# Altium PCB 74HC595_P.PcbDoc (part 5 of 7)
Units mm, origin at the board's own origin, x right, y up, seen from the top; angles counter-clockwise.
Board outline 89.11 x 89.03 mm, 2 copper layers (Top Layer, Bottom Layer); 552 components, 23 nets, 1488 pads, 408 vias.
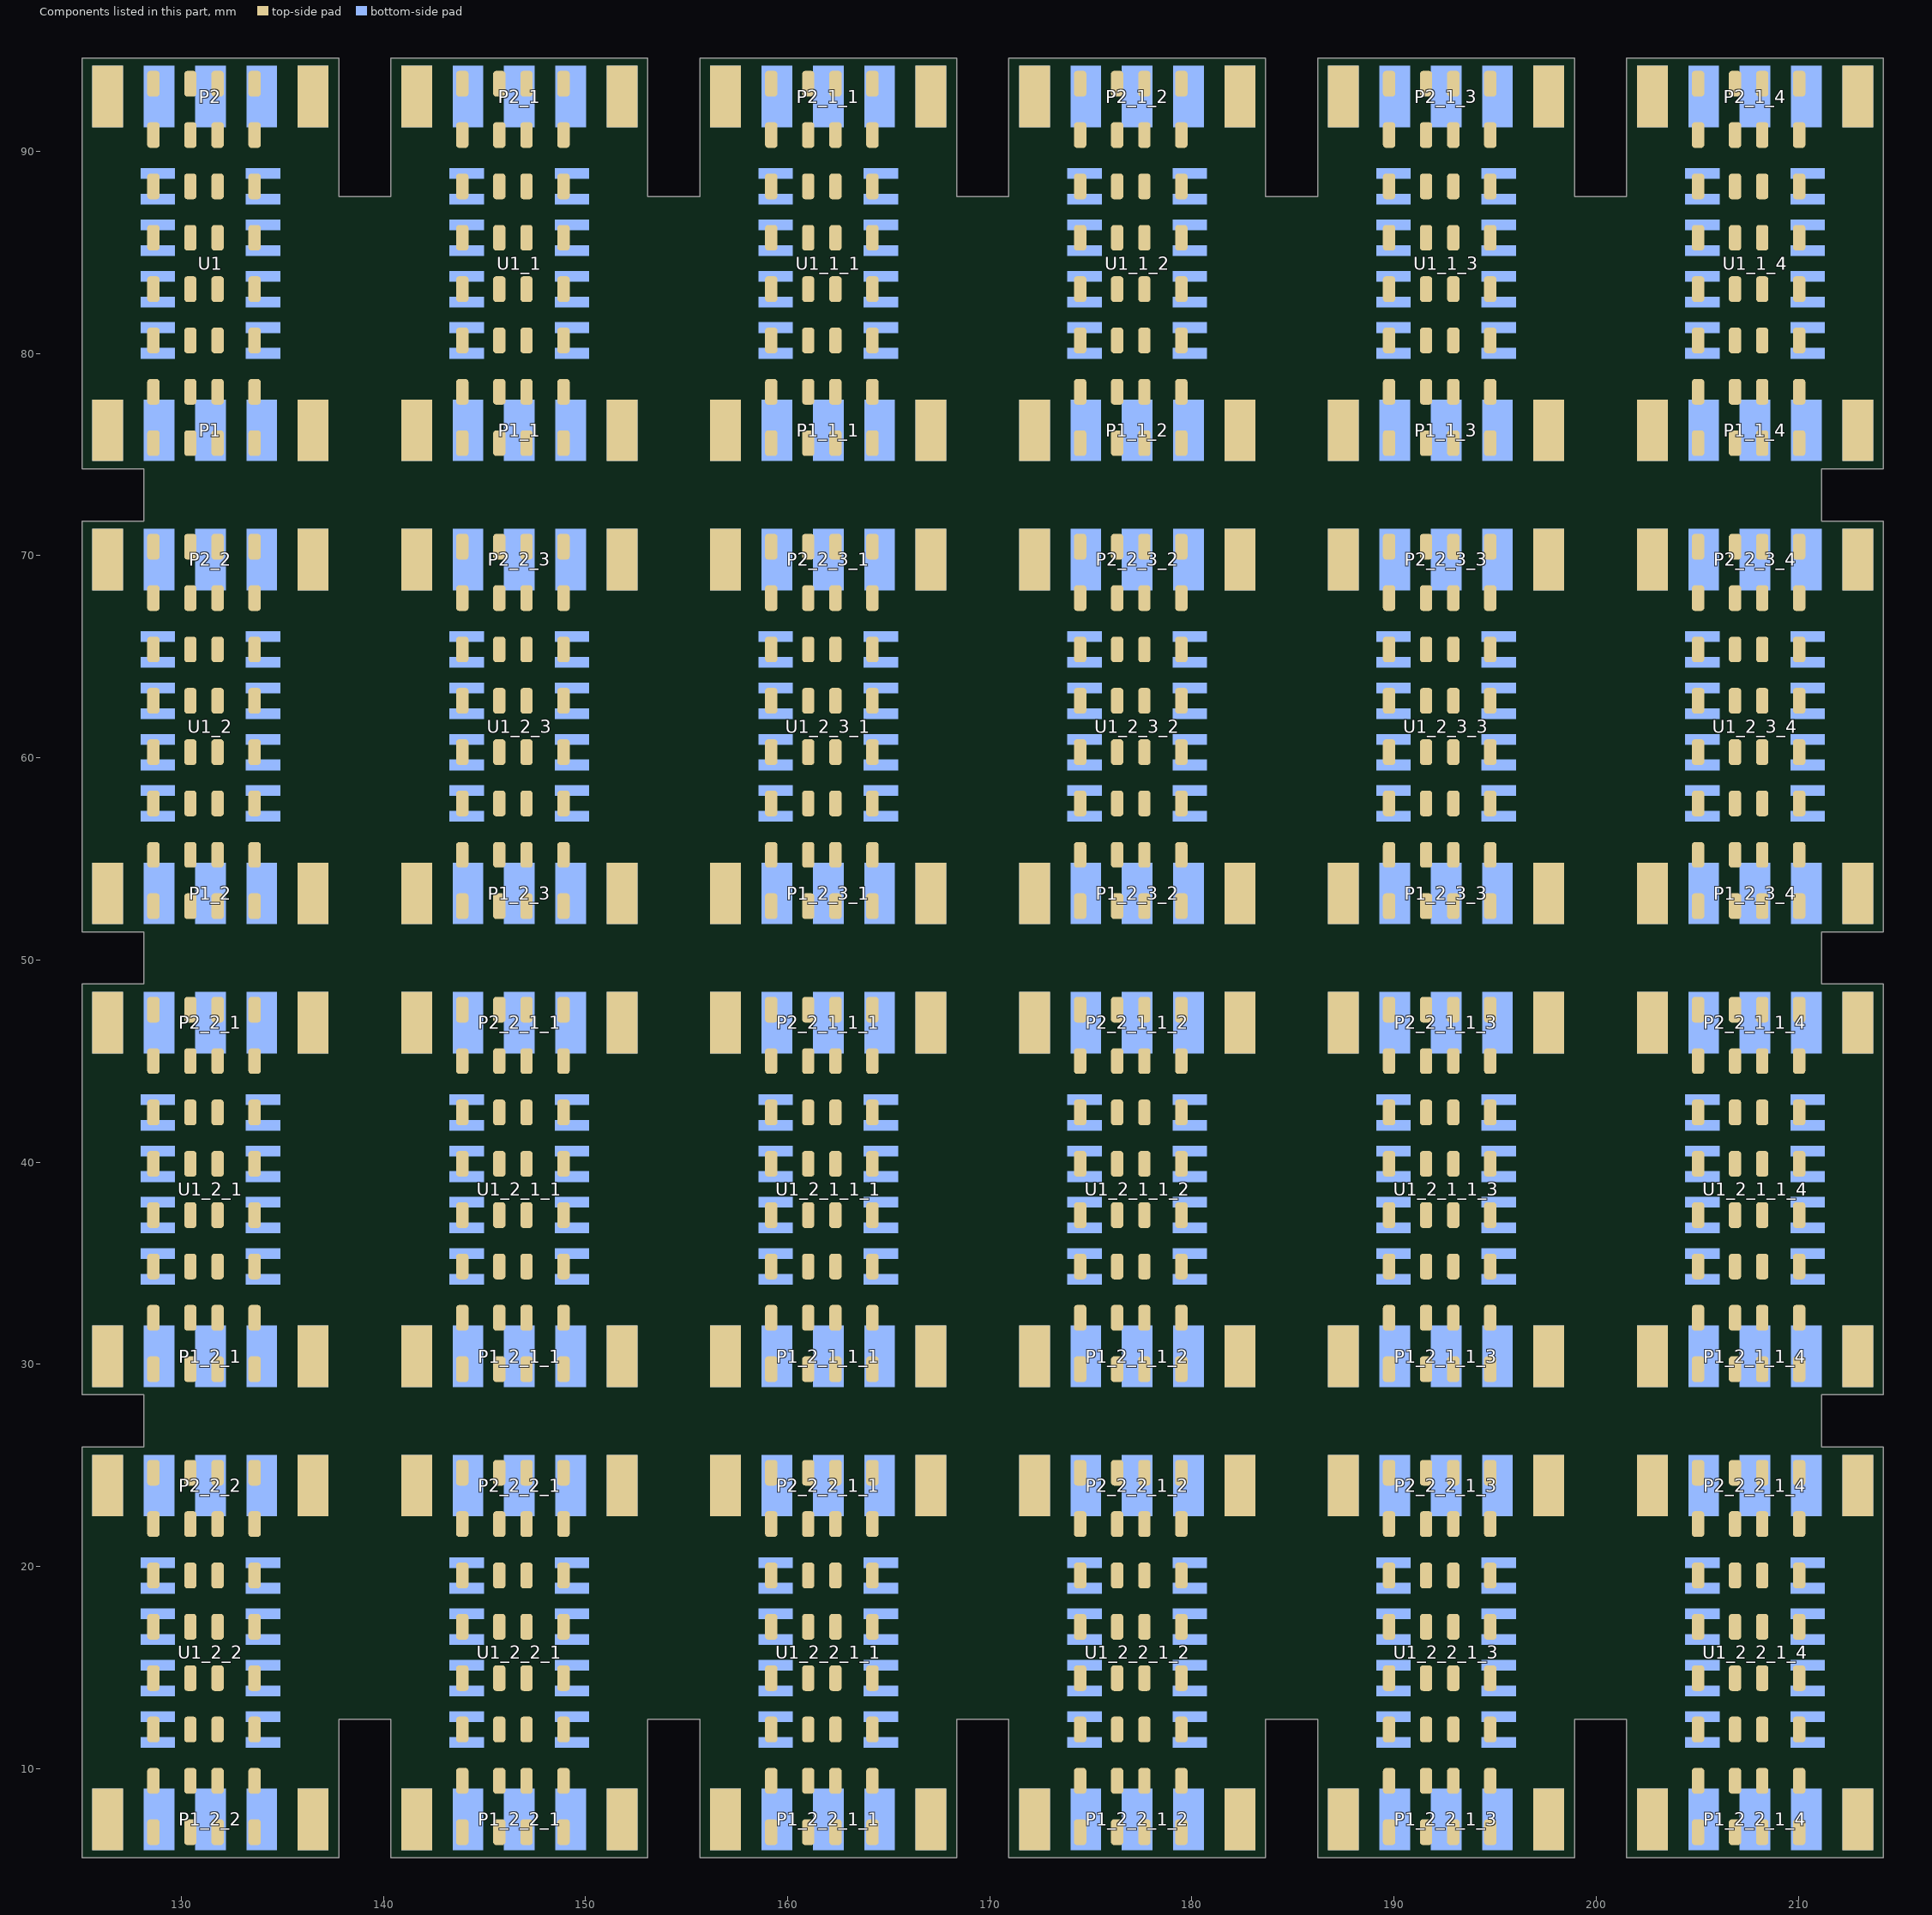
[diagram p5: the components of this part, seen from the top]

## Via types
v1: diameter 0.635, hole 0.381, Top Layer to Bottom Layer, 408 vias

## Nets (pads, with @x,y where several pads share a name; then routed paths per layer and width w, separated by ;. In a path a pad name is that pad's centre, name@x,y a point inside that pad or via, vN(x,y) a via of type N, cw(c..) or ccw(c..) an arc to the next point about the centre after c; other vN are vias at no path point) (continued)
copper on no net: | length 5395.2
  Top Layer w0.381: v1(126.746,16.765) v1(126.746,18.67) ; v1(126.746,39.667) v1(126.746,41.572) ; v1(126.746,62.569) v1(126.746,64.474) ; v1(127.508,15.749) v1(127.508,19.559) ; v1(127.508,38.651) v1(127.508,42.461) ; v1(127.508,61.553) v1(127.508,65.363) ; 130.454,6.859 131.801,6.859 ; 130.454,9.399 131.801,9.399 ; 130.454,11.939 131.801,11.939 ; 130.454,14.479 131.801,14.479 ; 130.454,17.019 131.801,17.019 ; 130.454,19.559 131.801,19.559 ; 130.454,22.099 131.801,22.099 ; 130.454,24.639 131.801,24.639 ; 130.454,29.761 131.801,29.761 ; 130.454,32.301 131.801,32.301 ; 130.454,34.841 131.801,34.841 ; 130.454,37.381 131.801,37.381 ; 130.454,39.921 131.801,39.921 ; 130.454,42.461 131.801,42.461 ; 130.454,45.001 131.801,45.001 ; 130.454,47.541 131.801,47.541 ; 130.454,52.663 131.801,52.663 ; 130.454,55.203 131.801,55.203 ; 130.454,57.743 131.801,57.743 ; 130.454,60.283 131.801,60.283 ; 130.454,62.823 131.801,62.823 ; 130.454,65.363 131.801,65.363 ; 130.454,67.903 131.801,67.903 ; 130.454,70.443 131.801,70.443 ; v1(131.191,15.749) 132.334,15.749 132.715,16.13 132.715,20.321 132.207,20.829 v1(131.191,20.829) ; v1(131.191,38.651) 132.334,38.651 132.715,39.032 132.715,43.223 132.207,43.731 v1(131.191,43.731) ; v1(131.191,61.553) 132.334,61.553 132.715,61.934 132.715,66.125 132.207,66.633 v1(131.191,66.633) ; 133.629,6.859 133.629,7.773 134.493,8.637 134.493,10.406 135.128,11.041 135.128,11.812 v1(135.89,12.574) ; 133.629,9.399 133.629,10.44 134.379,11.19 134.379,12.206 v1(136.017,13.844) ; 133.629,11.939 133.629,12.853 v1(135.89,15.114) ; 133.629,14.758 133.629,14.479 133.985,14.479 v1(135.89,16.384) ; 133.629,17.019 135.255,17.019 v1(135.89,17.654) ; 133.629,19.559 135.255,19.559 v1(135.89,18.924) ; 133.629,21.885 133.629,22.099 133.629,21.312 134.747,20.194 v1(135.89,20.194) ; 133.629,24.639 133.629,23.725 134.62,22.734 134.62,21.972 135.128,21.464 v1(135.89,21.464) ; 133.629,29.761 133.629,30.675 134.493,31.539 134.493,33.308 135.128,33.943 135.128,34.714 v1(135.89,35.476) ; 133.629,32.301 133.629,33.342 134.379,34.092 134.379,35.108 v1(136.017,36.746) ; 133.629,34.841 133.629,35.755 v1(135.89,38.016) ; 133.629,37.66 133.629,37.381 133.985,37.381 v1(135.89,39.286) ; 133.629,39.921 135.255,39.921 v1(135.89,40.556) ; 133.629,42.461 135.255,42.461 v1(135.89,41.826) ; 133.629,44.787 133.629,45.001 133.629,44.214 134.747,43.096 v1(135.89,43.096) ; 133.629,47.541 133.629,46.627 134.62,45.636 134.62,44.874 135.128,44.366 v1(135.89,44.366) ; 133.629,52.663 133.629,53.577 134.493,54.441 134.493,56.21 135.128,56.845 135.128,57.616 v1(135.89,58.378) ; 133.629,55.203 133.629,56.244 134.379,56.994 134.379,58.01 v1(136.017,59.648) ; 133.629,57.743 133.629,58.657 v1(135.89,60.918) ; 133.629,60.562 133.629,60.283 133.985,60.283 v1(135.89,62.188) ; 133.629,62.823 135.255,62.823 v1(135.89,63.458) ; 133.629,65.363 135.255,65.363 v1(135.89,64.728) ; 133.629,67.689 133.629,67.903 133.629,67.116 134.747,65.998 v1(135.89,65.998) ; 133.629,70.443 133.629,69.529 134.62,68.538 134.62,67.776 135.128,67.268 v1(135.89,67.268) ; v1(135.89,11.304) 137.033,11.304 ; v1(135.89,34.206) 137.033,34.206 ; v1(135.89,57.108) 137.033,57.108 ; v1(142.028,16.765) v1(142.028,18.67) ; v1(142.028,39.667) v1(142.028,41.572) ; v1(142.028,62.569) v1(142.028,64.474) ; v1(142.028,85.471) v1(142.028,87.376) ; v1(142.79,15.749) v1(142.79,19.559) ; v1(142.79,38.651) v1(142.79,42.461) ; v1(142.79,61.553) v1(142.79,65.363) ; v1(142.79,84.455) v1(142.79,88.265) ; 145.736,6.859 147.083,6.859 ; 145.736,9.399 147.083,9.399 ; 145.736,11.939 147.083,11.939 ; 145.736,14.479 147.083,14.479 ; 145.736,17.019 147.083,17.019 ; 145.736,19.559 147.083,19.559 ; 145.736,22.099 147.083,22.099 ; 145.736,24.639 147.083,24.639 ; 145.736,29.761 147.083,29.761 ; 145.736,32.301 147.083,32.301 ; 145.736,34.841 147.083,34.841 ; 145.736,37.381 147.083,37.381 ; 145.736,39.921 147.083,39.921 ; 145.736,42.461 147.083,42.461 ; 145.736,45.001 147.083,45.001 ; 145.736,47.541 147.083,47.541 ; 145.736,52.663 147.083,52.663 ; 145.736,55.203 147.083,55.203 ; 145.736,57.743 147.083,57.743 ; 145.736,60.283 147.083,60.283 ; 145.736,62.823 147.083,62.823 ; 145.736,65.363 147.083,65.363 ; 145.736,67.903 147.083,67.903 ; 145.736,70.443 147.083,70.443 ; 145.736,75.565 147.083,75.565 ; 145.736,78.105 147.083,78.105 ; 145.736,80.645 147.083,80.645 ; 145.736,83.185 147.083,83.185 ; 145.736,85.725 147.083,85.725 ; 145.736,88.265 147.083,88.265 ; 145.736,90.805 147.083,90.805 ; 145.736,93.345 147.083,93.345 ; v1(146.473,15.749) 147.616,15.749 147.997,16.13 147.997,20.321 147.489,20.829 v1(146.473,20.829) ; v1(146.473,38.651) 147.616,38.651 147.997,39.032 147.997,43.223 147.489,43.731 v1(146.473,43.731) ; v1(146.473,61.553) 147.616,61.553 147.997,61.934 147.997,66.125 147.489,66.633 v1(146.473,66.633) ; v1(146.473,84.455) 147.616,84.455 147.997,84.836 147.997,89.027 147.489,89.535 v1(146.473,89.535) ; 148.911,6.859 148.911,7.773 149.775,8.637 149.775,10.406 150.41,11.041 150.41,11.812 v1(151.172,12.574) ; 148.911,9.399 148.911,10.44 149.661,11.19 149.661,12.206 v1(151.299,13.844) ; 148.911,11.939 148.911,12.853 v1(151.172,15.114) ; 148.911,14.758 148.911,14.479 149.267,14.479 v1(151.172,16.384) ; 148.911,17.019 150.537,17.019 v1(151.172,17.654) ; 148.911,19.559 150.537,19.559 v1(151.172,18.924) ; 148.911,21.885 148.911,22.099 148.911,21.312 150.029,20.194 v1(151.172,20.194) ; 148.911,24.639 148.911,23.725 149.902,22.734 149.902,21.972 150.41,21.464 v1(151.172,21.464) ; 148.911,29.761 148.911,30.675 149.775,31.539 149.775,33.308 150.41,33.943 150.41,34.714 v1(151.172,35.476) ; 148.911,32.301 148.911,33.342 149.661,34.092 149.661,35.108 v1(151.299,36.746) ; 148.911,34.841 148.911,35.755 v1(151.172,38.016) ; 148.911,37.66 148.911,37.381 149.267,37.381 v1(151.172,39.286) ; 148.911,39.921 150.537,39.921 v1(151.172,40.556) ; 148.911,42.461 150.537,42.461 v1(151.172,41.826) ; 148.911,44.787 148.911,45.001 148.911,44.214 150.029,43.096 v1(151.172,43.096) ; 148.911,47.541 148.911,46.627 149.902,45.636 149.902,44.874 150.41,44.366 v1(151.172,44.366) ; 148.911,52.663 148.911,53.577 149.775,54.441 149.775,56.21 150.41,56.845 150.41,57.616 v1(151.172,58.378) ; 148.911,55.203 148.911,56.244 149.661,56.994 149.661,58.01 v1(151.299,59.648) ; 148.911,57.743 148.911,58.657 v1(151.172,60.918) ; 148.911,60.562 148.911,60.283 149.267,60.283 v1(151.172,62.188) ; 148.911,62.823 150.537,62.823 v1(151.172,63.458) ; 148.911,65.363 150.537,65.363 v1(151.172,64.728) ; 148.911,67.689 148.911,67.903 148.911,67.116 150.029,65.998 v1(151.172,65.998) ; 148.911,70.443 148.911,69.529 149.902,68.538 149.902,67.776 150.41,67.268 v1(151.172,67.268) ; 148.911,75.565 148.911,76.479 149.775,77.343 149.775,79.112 150.41,79.747 150.41,80.518 v1(151.172,81.28) ; 148.911,78.105 148.911,79.146 149.661,79.896 149.661,80.912 v1(151.299,82.55) ; 148.911,80.645 148.911,81.559 v1(151.172,83.82) ; 148.911,83.464 148.911,83.185 149.267,83.185 v1(151.172,85.09) ; 148.911,85.725 150.537,85.725 v1(151.172,86.36) ; 148.911,88.265 150.537,88.265 v1(151.172,87.63) ; 148.911,90.591 148.911,90.805 148.911,90.018 150.029,88.9 v1(151.172,88.9) ; 148.911,93.345 148.911,92.431 149.902,91.44 149.902,90.678 150.41,90.17 v1(151.172,90.17) ; v1(151.172,11.304) 152.315,11.304 ; v1(151.172,34.206) 152.315,34.206 ; v1(151.172,57.108) 152.315,57.108 ; v1(151.172,80.01) 152.315,80.01 ; v1(157.31,16.765) v1(157.31,18.67) ; v1(157.31,39.667) v1(157.31,41.572) ; v1(157.31,62.569) v1(157.31,64.474) ; v1(157.31,85.471) v1(157.31,87.376) ; v1(158.072,15.749) v1(158.072,19.559) ; v1(158.072,38.651) v1(158.072,42.461) ; v1(158.072,61.553) v1(158.072,65.363) ; v1(158.072,84.455) v1(158.072,88.265) ; 161.018,6.859 162.365,6.859 ; 161.018,9.399 162.365,9.399 ; 161.018,11.939 162.365,11.939 ; 161.018,14.479 162.365,14.479 ; 161.018,17.019 162.365,17.019 ; 161.018,19.559 162.365,19.559 ; 161.018,22.099 162.365,22.099 ; 161.018,24.639 162.365,24.639 ; 161.018,29.761 162.365,29.761 ; 161.018,32.301 162.365,32.301 ; 161.018,34.841 162.365,34.841 ; 161.018,37.381 162.365,37.381 ; 161.018,39.921 162.365,39.921 ; 161.018,42.461 162.365,42.461 ; 161.018,45.001 162.365,45.001 ; 161.018,47.541 162.365,47.541 ; 161.018,52.663 162.365,52.663 ; 161.018,55.203 162.365,55.203 ; 161.018,57.743 162.365,57.743 ; 161.018,60.283 162.365,60.283 ; 161.018,62.823 162.365,62.823 ; 161.018,65.363 162.365,65.363 ; 161.018,67.903 162.365,67.903 ; 161.018,70.443 162.365,70.443 ; 161.018,75.565 162.365,75.565 ; 161.018,78.105 162.365,78.105 ; 161.018,80.645 162.365,80.645 ; 161.018,83.185 162.365,83.185 ; 161.018,85.725 162.365,85.725 ; 161.018,88.265 162.365,88.265 ; 161.018,90.805 162.365,90.805 ; 161.018,93.345 162.365,93.345 ; v1(161.755,15.749) 162.898,15.749 163.279,16.13 163.279,20.321 162.771,20.829 v1(161.755,20.829) ; v1(161.755,38.651) 162.898,38.651 163.279,39.032 163.279,43.223 162.771,43.731 v1(161.755,43.731) ; v1(161.755,61.553) 162.898,61.553 163.279,61.934 163.279,66.125 162.771,66.633 v1(161.755,66.633) ; v1(161.755,84.455) 162.898,84.455 163.279,84.836 163.279,89.027 162.771,89.535 v1(161.755,89.535) ; 164.193,6.859 164.193,7.773 165.057,8.637 165.057,10.406 165.692,11.041 165.692,11.812 v1(166.454,12.574) ; 164.193,9.399 164.193,10.44 164.943,11.19 164.943,12.206 v1(166.581,13.844) ; 164.193,11.939 164.193,12.853 v1(166.454,15.114) ; 164.193,14.758 164.193,14.479 164.549,14.479 v1(166.454,16.384) ; 164.193,17.019 165.819,17.019 v1(166.454,17.654) ; 164.193,19.559 165.819,19.559 v1(166.454,18.924) ; 164.193,21.885 164.193,22.099 164.193,21.312 165.311,20.194 v1(166.454,20.194) ; 164.193,24.639 164.193,23.725 165.184,22.734 165.184,21.972 165.692,21.464 v1(166.454,21.464) ; 164.193,29.761 164.193,30.675 165.057,31.539 165.057,33.308 165.692,33.943 165.692,34.714 v1(166.454,35.476) ; 164.193,32.301 164.193,33.342 164.943,34.092 164.943,35.108 v1(166.581,36.746) ; 164.193,34.841 164.193,35.755 v1(166.454,38.016) ; 164.193,37.66 164.193,37.381 164.549,37.381 v1(166.454,39.286) ; 164.193,39.921 165.819,39.921 v1(166.454,40.556) ; 164.193,42.461 165.819,42.461 v1(166.454,41.826) ; 164.193,44.787 164.193,45.001 164.193,44.214 165.311,43.096 v1(166.454,43.096) ; 164.193,47.541 164.193,46.627 165.184,45.636 165.184,44.874 165.692,44.366 v1(166.454,44.366) ; 164.193,52.663 164.193,53.577 165.057,54.441 165.057,56.21 165.692,56.845 165.692,57.616 v1(166.454,58.378) ; 164.193,55.203 164.193,56.244 164.943,56.994 164.943,58.01 v1(166.581,59.648) ; 164.193,57.743 164.193,58.657 v1(166.454,60.918) ; 164.193,60.562 164.193,60.283 164.549,60.283 v1(166.454,62.188) ; 164.193,62.823 165.819,62.823 v1(166.454,63.458) ; 164.193,65.363 165.819,65.363 v1(166.454,64.728) ; 164.193,67.689 164.193,67.903 164.193,67.116 165.311,65.998 v1(166.454,65.998) ; 164.193,70.443 164.193,69.529 165.184,68.538 165.184,67.776 165.692,67.268 v1(166.454,67.268) ; 164.193,75.565 164.193,76.479 165.057,77.343 165.057,79.112 165.692,79.747 165.692,80.518 v1(166.454,81.28) ; 164.193,78.105 164.193,79.146 164.943,79.896 164.943,80.912 v1(166.581,82.55) ; 164.193,80.645 164.193,81.559 v1(166.454,83.82) ; 164.193,83.464 164.193,83.185 164.549,83.185 v1(166.454,85.09) ; 164.193,85.725 165.819,85.725 v1(166.454,86.36) ; 164.193,88.265 165.819,88.265 v1(166.454,87.63) ; 164.193,90.591 164.193,90.805 164.193,90.018 165.311,88.9 v1(166.454,88.9) ; 164.193,93.345 164.193,92.431 165.184,91.44 165.184,90.678 165.692,90.17 v1(166.454,90.17) ; v1(166.454,11.304) 167.597,11.304 ; v1(166.454,34.206) 167.597,34.206 ; v1(166.454,57.108) 167.597,57.108 ; v1(166.454,80.01) 167.597,80.01 ; v1(172.592,16.765) v1(172.592,18.67) ; v1(172.592,39.667) v1(172.592,41.572) ; v1(172.592,62.569) v1(172.592,64.474) ; v1(172.592,85.471) v1(172.592,87.376) ; v1(173.354,15.749) v1(173.354,19.559) ; v1(173.354,38.651) v1(173.354,42.461) ; v1(173.354,61.553) v1(173.354,65.363) ; v1(173.354,84.455) v1(173.354,88.265) ; 176.3,6.859 177.647,6.859 ; 176.3,9.399 177.647,9.399 ; 176.3,11.939 177.647,11.939 ; 176.3,14.479 177.647,14.479 ; 176.3,17.019 177.647,17.019 ; 176.3,19.559 177.647,19.559 ; 176.3,22.099 177.647,22.099 ; 176.3,24.639 177.647,24.639 ; 176.3,29.761 177.647,29.761 ; 176.3,32.301 177.647,32.301 ; 176.3,34.841 177.647,34.841 ; 176.3,37.381 177.647,37.381 ; 176.3,39.921 177.647,39.921 ; 176.3,42.461 177.647,42.461 ; 176.3,45.001 177.647,45.001 ; 176.3,47.541 177.647,47.541 ; 176.3,52.663 177.647,52.663 ; 176.3,55.203 177.647,55.203 ; 176.3,57.743 177.647,57.743 ; 176.3,60.283 177.647,60.283 ; 176.3,62.823 177.647,62.823 ; 176.3,65.363 177.647,65.363 ; 176.3,67.903 177.647,67.903 ; 176.3,70.443 177.647,70.443 ; 176.3,75.565 177.647,75.565 ; 176.3,78.105 177.647,78.105 ; 176.3,80.645 177.647,80.645 ; 176.3,83.185 177.647,83.185 ; 176.3,85.725 177.647,85.725 ; 176.3,88.265 177.647,88.265 ; 176.3,90.805 177.647,90.805 ; 176.3,93.345 177.647,93.345 ; v1(177.037,15.749) 178.18,15.749 178.561,16.13 178.561,20.321 178.053,20.829 v1(177.037,20.829) ; v1(177.037,38.651) 178.18,38.651 178.561,39.032 178.561,43.223 178.053,43.731 v1(177.037,43.731) ; v1(177.037,61.553) 178.18,61.553 178.561,61.934 178.561,66.125 178.053,66.633 v1(177.037,66.633) ; v1(177.037,84.455) 178.18,84.455 178.561,84.836 178.561,89.027 178.053,89.535 v1(177.037,89.535) ; 179.475,6.859 179.475,7.773 180.339,8.637 180.339,10.406 180.974,11.041 180.974,11.812 v1(181.736,12.574) ; 179.475,9.399 179.475,10.44 180.225,11.19 180.225,12.206 v1(181.863,13.844) ; 179.475,11.939 179.475,12.853 v1(181.736,15.114) ; 179.475,14.758 179.475,14.479 179.831,14.479 v1(181.736,16.384) ; 179.475,17.019 181.101,17.019 v1(181.736,17.654) ; 179.475,19.559 181.101,19.559 v1(181.736,18.924) ; 179.475,21.885 179.475,22.099 179.475,21.312 180.593,20.194 v1(181.736,20.194) ; 179.475,24.639 179.475,23.725 180.466,22.734 180.466,21.972 180.974,21.464 v1(181.736,21.464) ; 179.475,29.761 179.475,30.675 180.339,31.539 180.339,33.308 180.974,33.943 180.974,34.714 v1(181.736,35.476) ; 179.475,32.301 179.475,33.342 180.225,34.092 180.225,35.108 v1(181.863,36.746) ; 179.475,34.841 179.475,35.755 v1(181.736,38.016) ; 179.475,37.66 179.475,37.381 179.831,37.381 v1(181.736,39.286) ; 179.475,39.921 181.101,39.921 v1(181.736,40.556) ; 179.475,42.461 181.101,42.461 v1(181.736,41.826) ; 179.475,44.787 179.475,45.001 179.475,44.214 180.593,43.096 v1(181.736,43.096) ; 179.475,47.541 179.475,46.627 180.466,45.636 180.466,44.874 180.974,44.366 v1(181.736,44.366) ; 179.475,52.663 179.475,53.577 180.339,54.441 180.339,56.21 180.974,56.845 180.974,57.616 v1(181.736,58.378) ; 179.475,55.203 179.475,56.244 180.225,56.994 180.225,58.01 v1(181.863,59.648) ; 179.475,57.743 179.475,58.657 v1(181.736,60.918) ; 179.475,60.562 179.475,60.283 179.831,60.283 v1(181.736,62.188) ; 179.475,62.823 181.101,62.823 v1(181.736,63.458) ; 179.475,65.363 181.101,65.363 v1(181.736,64.728) ; 179.475,67.689 179.475,67.903 179.475,67.116 180.593,65.998 v1(181.736,65.998) ; 179.475,70.443 179.475,69.529 180.466,68.538 180.466,67.776 180.974,67.268 v1(181.736,67.268) ; 179.475,75.565 179.475,76.479 180.339,77.343 180.339,79.112 180.974,79.747 180.974,80.518 v1(181.736,81.28) ; 179.475,78.105 179.475,79.146 180.225,79.896 180.225,80.912 v1(181.863,82.55) ; 179.475,80.645 179.475,81.559 v1(181.736,83.82) ; 179.475,83.464 179.475,83.185 179.831,83.185 v1(181.736,85.09) ; 179.475,85.725 181.101,85.725 v1(181.736,86.36) ; 179.475,88.265 181.101,88.265 v1(181.736,87.63) ; 179.475,90.591 179.475,90.805 179.475,90.018 180.593,88.9 v1(181.736,88.9) ; 179.475,93.345 179.475,92.431 180.466,91.44 180.466,90.678 180.974,90.17 v1(181.736,90.17) ; v1(181.736,11.304) 182.879,11.304 ; v1(181.736,34.206) 182.879,34.206 ; v1(181.736,57.108) 182.879,57.108 ; v1(181.736,80.01) 182.879,80.01 ; v1(187.874,16.765) v1(187.874,18.67) ; v1(187.874,39.667) v1(187.874,41.572) ; v1(187.874,62.569) v1(187.874,64.474) ; v1(187.874,85.471) v1(187.874,87.376) ; v1(188.636,15.749) v1(188.636,19.559) ; v1(188.636,38.651) v1(188.636,42.461) ; v1(188.636,61.553) v1(188.636,65.363) ; v1(188.636,84.455) v1(188.636,88.265) ; 191.582,6.859 192.929,6.859 ; 191.582,9.399 192.929,9.399 ; 191.582,11.939 192.929,11.939 ; 191.582,14.479 192.929,14.479 ; 191.582,17.019 192.929,17.019 ; 191.582,19.559 192.929,19.559 ; 191.582,22.099 192.929,22.099 ; 191.582,24.639 192.929,24.639 ; 191.582,29.761 192.929,29.761 ; 191.582,32.301 192.929,32.301 ; 191.582,34.841 192.929,34.841 ; 191.582,37.381 192.929,37.381 ; 191.582,39.921 192.929,39.921 ; 191.582,42.461 192.929,42.461 ; 191.582,45.001 192.929,45.001 ; 191.582,47.541 192.929,47.541 ; 191.582,52.663 192.929,52.663 ; 191.582,55.203 192.929,55.203 ; 191.582,57.743 192.929,57.743 ; 191.582,60.283 192.929,60.283 ; 191.582,62.823 192.929,62.823 ; 191.582,65.363 192.929,65.363 ; 191.582,67.903 192.929,67.903 ; 191.582,70.443 192.929,70.443 ; 191.582,75.565 192.929,75.565 ; 191.582,78.105 192.929,78.105 ; 191.582,80.645 192.929,80.645 ; 191.582,83.185 192.929,83.185 ; 191.582,85.725 192.929,85.725 ; 191.582,88.265 192.929,88.265 ; 191.582,90.805 192.929,90.805 ; 191.582,93.345 192.929,93.345 ; v1(192.319,15.749) 193.462,15.749 193.843,16.13 193.843,20.321 193.335,20.829 v1(192.319,20.829) ; v1(192.319,38.651) 193.462,38.651 193.843,39.032 193.843,43.223 193.335,43.731 v1(192.319,43.731) ; v1(192.319,61.553) 193.462,61.553 193.843,61.934 193.843,66.125 193.335,66.633 v1(192.319,66.633) ; v1(192.319,84.455) 193.462,84.455 193.843,84.836 193.843,89.027 193.335,89.535 v1(192.319,89.535) ; 194.757,6.859 194.757,7.773 195.621,8.637 195.621,10.406 196.256,11.041 196.256,11.812 v1(197.018,12.574) ; 194.757,9.399 194.757,10.44 195.507,11.19 195.507,12.206 v1(197.145,13.844) ; 194.757,11.939 194.757,12.853 v1(197.018,15.114) ; 194.757,14.758 194.757,14.479 195.113,14.479 v1(197.018,16.384) ; 194.757,17.019 196.383,17.019 v1(197.018,17.654) ; 194.757,19.559 196.383,19.559 v1(197.018,18.924) ; 194.757,21.885 194.757,22.099 194.757,21.312 195.875,20.194 v1(197.018,20.194) ; 194.757,24.639 194.757,23.725 195.748,22.734 195.748,21.972 196.256,21.464 v1(197.018,21.464) ; 194.757,29.761 194.757,30.675 195.621,31.539 195.621,33.308 196.256,33.943 196.256,34.714 v1(197.018,35.476) ; 194.757,32.301 194.757,33.342 195.507,34.092 195.507,35.108 v1(197.145,36.746) ; 194.757,34.841 194.757,35.755 v1(197.018,38.016) ; 194.757,37.66 194.757,37.381 195.113,37.381 v1(197.018,39.286) ; 194.757,39.921 196.383,39.921 v1(197.018,40.556) ; 194.757,42.461 196.383,42.461 v1(197.018,41.826) ; 194.757,44.787 194.757,45.001 194.757,44.214 195.875,43.096 v1(197.018,43.096) ; 194.757,47.541 194.757,46.627 195.748,45.636 195.748,44.874 196.256,44.366 v1(197.018,44.366) ; 194.757,52.663 194.757,53.577 195.621,54.441 195.621,56.21 196.256,56.845 196.256,57.616 v1(197.018,58.378) ; 194.757,55.203 194.757,56.244 195.507,56.994 195.507,58.01 v1(197.145,59.648) ; 194.757,57.743 194.757,58.657 v1(197.018,60.918) ; 194.757,60.562 194.757,60.283 195.113,60.283 v1(197.018,62.188) ; 194.757,62.823 196.383,62.823 v1(197.018,63.458) ; 194.757,65.363 196.383,65.363 v1(197.018,64.728) ; 194.757,67.689 194.757,67.903 194.757,67.116 195.875,65.998 v1(197.018,65.998) ; 194.757,70.443 194.757,69.529 195.748,68.538 195.748,67.776 196.256,67.268 v1(197.018,67.268) ; 194.757,75.565 194.757,76.479 195.621,77.343 195.621,79.112 196.256,79.747 196.256,80.518 v1(197.018,81.28) ; 194.757,78.105 194.757,79.146 195.507,79.896 195.507,80.912 v1(197.145,82.55) ; 194.757,80.645 194.757,81.559 v1(197.018,83.82) ; 194.757,83.464 194.757,83.185 195.113,83.185 v1(197.018,85.09) ; 194.757,85.725 196.383,85.725 v1(197.018,86.36) ; 194.757,88.265 196.383,88.265 v1(197.018,87.63) ; 194.757,90.591 194.757,90.805 194.757,90.018 195.875,88.9 v1(197.018,88.9) ; 194.757,93.345 194.757,92.431 195.748,91.44 195.748,90.678 196.256,90.17 v1(197.018,90.17) ; v1(197.018,11.304) 198.161,11.304 ; v1(197.018,34.206) 198.161,34.206 ; v1(197.018,57.108) 198.161,57.108 ; v1(197.018,80.01) 198.161,80.01 ; v1(203.156,16.765) v1(203.156,18.67) ; v1(203.156,39.667) v1(203.156,41.572) ; v1(203.156,62.569) v1(203.156,64.474) ; v1(203.156,85.471) v1(203.156,87.376) ; v1(203.918,15.749) v1(203.918,19.559) ; v1(203.918,38.651) v1(203.918,42.461) ; v1(203.918,61.553) v1(203.918,65.363) ; v1(203.918,84.455) v1(203.918,88.265) ; 206.864,6.859 208.211,6.859 ; 206.864,9.399 208.211,9.399 ; 206.864,11.939 208.211,11.939 ; 206.864,14.479 208.211,14.479 ; 206.864,17.019 208.211,17.019 ; 206.864,19.559 208.211,19.559 ; 206.864,22.099 208.211,22.099 ; 206.864,24.639 208.211,24.639 ; 206.864,29.761 208.211,29.761 ; 206.864,32.301 208.211,32.301 ; 206.864,34.841 208.211,34.841 ; 206.864,37.381 208.211,37.381 ; 206.864,39.921 208.211,39.921 ; 206.864,42.461 208.211,42.461 ; 206.864,45.001 208.211,45.001 ; 206.864,47.541 208.211,47.541 ; 206.864,52.663 208.211,52.663 ; 206.864,55.203 208.211,55.203 ; 206.864,57.743 208.211,57.743 ; 206.864,60.283 208.211,60.283 ; 206.864,62.823 208.211,62.823 ; 206.864,65.363 208.211,65.363 ; 206.864,67.903 208.211,67.903 ; 206.864,70.443 208.211,70.443 ; 206.864,75.565 208.211,75.565 ; 206.864,78.105 208.211,78.105 ; 206.864,80.645 208.211,80.645 ; 206.864,83.185 208.211,83.185 ; 206.864,85.725 208.211,85.725 ; 206.864,88.265 208.211,88.265 ; 206.864,90.805 208.211,90.805 ; 206.864,93.345 208.211,93.345 ; v1(207.601,15.749) 208.744,15.749 209.125,16.13 209.125,20.321 208.617,20.829 v1(207.601,20.829) ; v1(207.601,38.651) 208.744,38.651 209.125,39.032 209.125,43.223 208.617,43.731 v1(207.601,43.731) ; v1(207.601,61.553) 208.744,61.553 209.125,61.934 209.125,66.125 208.617,66.633 v1(207.601,66.633) ; v1(207.601,84.455) 208.744,84.455 209.125,84.836 209.125,89.027 208.617,89.535 v1(207.601,89.535) ; 210.039,6.859 210.039,7.773 210.903,8.637 210.903,10.406 211.538,11.041 211.538,11.812 v1(212.3,12.574) ; 210.039,9.399 210.039,10.44 210.789,11.19 210.789,12.206 v1(212.427,13.844) ; 210.039,11.939 210.039,12.853 v1(212.3,15.114) ; 210.039,14.758 210.039,14.479 210.395,14.479 v1(212.3,16.384) ; 210.039,17.019 211.665,17.019 v1(212.3,17.654) ; 210.039,19.559 211.665,19.559 v1(212.3,18.924) ; 210.039,21.885 210.039,22.099 210.039,21.312 211.157,20.194 v1(212.3,20.194) ; 210.039,24.639 210.039,23.725 211.03,22.734 211.03,21.972 211.538,21.464 v1(212.3,21.464) ; 210.039,29.761 210.039,30.675 210.903,31.539 210.903,33.308 211.538,33.943 211.538,34.714 v1(212.3,35.476) ; 210.039,32.301 210.039,33.342 210.789,34.092 210.789,35.108 v1(212.427,36.746) ; 210.039,34.841 210.039,35.755 v1(212.3,38.016) ; 210.039,37.66 210.039,37.381 210.395,37.381 v1(212.3,39.286) ; 210.039,39.921 211.665,39.921 v1(212.3,40.556) ; 210.039,42.461 211.665,42.461 v1(212.3,41.826) ; 210.039,44.787 210.039,45.001 210.039,44.214 211.157,43.096 v1(212.3,43.096) ; 210.039,47.541 210.039,46.627 211.03,45.636 211.03,44.874 211.538,44.366 v1(212.3,44.366) ; 210.039,52.663 210.039,53.577 210.903,54.441 210.903,56.21 211.538,56.845 211.538,57.616 v1(212.3,58.378) ; 210.039,55.203 210.039,56.244 210.789,56.994 210.789,58.01 v1(212.427,59.648) ; 210.039,57.743 210.039,58.657 v1(212.3,60.918) ; 210.039,60.562 210.039,60.283 210.395,60.283 v1(212.3,62.188) ; 210.039,62.823 211.665,62.823 v1(212.3,63.458) ; 210.039,65.363 211.665,65.363 v1(212.3,64.728) ; 210.039,67.689 210.039,67.903 210.039,67.116 211.157,65.998 v1(212.3,65.998) ; 210.039,70.443 210.039,69.529 211.03,68.538 211.03,67.776 211.538,67.268 v1(212.3,67.268) ; 210.039,75.565 210.039,76.479 210.903,77.343 210.903,79.112 211.538,79.747 211.538,80.518 v1(212.3,81.28) ; 210.039,78.105 210.039,79.146 210.789,79.896 210.789,80.912 v1(212.427,82.55) ; 210.039,80.645 210.039,81.559 v1(212.3,83.82) ; 210.039,83.464 210.039,83.185 210.395,83.185 v1(212.3,85.09) ; 210.039,85.725 211.665,85.725 v1(212.3,86.36) ; 210.039,88.265 211.665,88.265 v1(212.3,87.63) ; 210.039,90.591 210.039,90.805 210.039,90.018 211.157,88.9 v1(212.3,88.9) ; 210.039,93.345 210.039,92.431 211.03,91.44 211.03,90.678 211.538,90.17 v1(212.3,90.17) ; v1(212.3,11.304) 213.443,11.304 ; v1(212.3,34.206) 213.443,34.206 ; v1(212.3,57.108) 213.443,57.108 ; v1(212.3,80.01) 213.443,80.01
  Top Layer w0.508: 125.857,8.764 125.857,22.734 ; 125.857,31.666 125.857,45.636 ; 125.857,54.568 125.857,68.538 ; 125.984,12.574 v1(127.635,12.574) 128.626,12.574 ; 125.984,20.829 v1(128.626,20.829) ; 125.984,35.476 v1(127.635,35.476) 128.626,35.476 ; 125.984,43.731 v1(128.626,43.731) ; 125.984,58.378 v1(127.635,58.378) 128.626,58.378 ; 125.984,66.633 v1(128.626,66.633) ; 128.626,6.859 128.626,9.399 128.626,11.939 128.626,14.479 128.626,17.019 128.626,19.559 v1(128.626,20.829) ; 128.626,24.639 128.626,22.099 v1(128.626,20.829) ; 128.626,29.761 128.626,32.301 128.626,34.841 128.626,37.381 128.626,39.921 128.626,42.461 v1(128.626,43.731) ; 128.626,47.541 128.626,45.001 v1(128.626,43.731) ; 128.626,52.663 128.626,55.203 128.626,57.743 128.626,60.283 128.626,62.823 128.626,65.363 v1(128.626,66.633) ; 128.626,70.443 128.626,67.903 v1(128.626,66.633) ; 137.033,8.764 137.033,11.304 137.033,22.734 ; 137.033,31.666 137.033,34.206 137.033,45.636 ; 137.033,54.568 137.033,57.108 137.033,68.538 ; 141.139,8.764 141.139,22.734 ; 141.139,31.666 141.139,45.636 ; 141.139,54.568 141.139,68.538 ; 141.139,77.47 141.139,91.44 ; 141.266,12.574 v1(142.917,12.574) 143.908,12.574 ; 141.266,20.829 v1(143.908,20.829) ; 141.266,35.476 v1(142.917,35.476) 143.908,35.476 ; 141.266,43.731 v1(143.908,43.731) ; 141.266,58.378 v1(142.917,58.378) 143.908,58.378 ; 141.266,66.633 v1(143.908,66.633) ; 141.266,81.28 v1(142.917,81.28) 143.908,81.28 ; 141.266,89.535 v1(143.908,89.535) ; 143.908,6.859 143.908,9.399 143.908,11.939 143.908,14.479 143.908,17.019 143.908,19.559 v1(143.908,20.829) ; 143.908,24.639 143.908,22.099 v1(143.908,20.829) ; 143.908,29.761 143.908,32.301 143.908,34.841 143.908,37.381 143.908,39.921 143.908,42.461 v1(143.908,43.731) ; 143.908,47.541 143.908,45.001 v1(143.908,43.731) ; 143.908,52.663 143.908,55.203 143.908,57.743 143.908,60.283 143.908,62.823 143.908,65.363 v1(143.908,66.633) ; 143.908,70.443 143.908,67.903 v1(143.908,66.633) ; 143.908,75.565 143.908,78.105 143.908,80.645 143.908,83.185 143.908,85.725 143.908,88.265 v1(143.908,89.535) ; 143.908,93.345 143.908,90.805 v1(143.908,89.535) ; 152.315,8.764 152.315,11.304 152.315,22.734 ; 152.315,31.666 152.315,34.206 152.315,45.636 ; 152.315,54.568 152.315,57.108 152.315,68.538 ; 152.315,77.47 152.315,80.01 152.315,91.44 ; 156.421,8.764 156.421,22.734 ; 156.421,31.666 156.421,45.636 ; 156.421,54.568 156.421,68.538 ; 156.421,77.47 156.421,91.44 ; 156.548,12.574 v1(158.199,12.574) 159.19,12.574 ; 156.548,20.829 v1(159.19,20.829) ; 156.548,35.476 v1(158.199,35.476) 159.19,35.476 ; 156.548,43.731 v1(159.19,43.731) ; 156.548,58.378 v1(158.199,58.378) 159.19,58.378 ; 156.548,66.633 v1(159.19,66.633) ; 156.548,81.28 v1(158.199,81.28) 159.19,81.28 ; 156.548,89.535 v1(159.19,89.535) ; 159.19,6.859 159.19,9.399 159.19,11.939 159.19,14.479 159.19,17.019 159.19,19.559 v1(159.19,20.829) ; 159.19,24.639 159.19,22.099 v1(159.19,20.829) ; 159.19,29.761 159.19,32.301 159.19,34.841 159.19,37.381 159.19,39.921 159.19,42.461 v1(159.19,43.731) ; 159.19,47.541 159.19,45.001 v1(159.19,43.731) ; 159.19,52.663 159.19,55.203 159.19,57.743 159.19,60.283 159.19,62.823 159.19,65.363 v1(159.19,66.633) ; 159.19,70.443 159.19,67.903 v1(159.19,66.633) ; 159.19,75.565 159.19,78.105 159.19,80.645 159.19,83.185 159.19,85.725 159.19,88.265 v1(159.19,89.535) ; 159.19,93.345 159.19,90.805 v1(159.19,89.535) ; 167.597,8.764 167.597,11.304 167.597,22.734 ; 167.597,31.666 167.597,34.206 167.597,45.636 ; 167.597,54.568 167.597,57.108 167.597,68.538 ; 167.597,77.47 167.597,80.01 167.597,91.44 ; 171.703,8.764 171.703,22.734 ; 171.703,31.666 171.703,45.636 ; 171.703,54.568 171.703,68.538 ; 171.703,77.47 171.703,91.44 ; 171.83,12.574 v1(173.481,12.574) 174.472,12.574 ; 171.83,20.829 v1(174.472,20.829) ; 171.83,35.476 v1(173.481,35.476) 174.472,35.476 ; 171.83,43.731 v1(174.472,43.731) ; 171.83,58.378 v1(173.481,58.378) 174.472,58.378 ; 171.83,66.633 v1(174.472,66.633) ; 171.83,81.28 v1(173.481,81.28) 174.472,81.28 ; 171.83,89.535 v1(174.472,89.535) ; 174.472,6.859 174.472,9.399 174.472,11.939 174.472,14.479 174.472,17.019 174.472,19.559 v1(174.472,20.829) ; 174.472,24.639 174.472,22.099 v1(174.472,20.829) ; 174.472,29.761 174.472,32.301 174.472,34.841 174.472,37.381 174.472,39.921 174.472,42.461 v1(174.472,43.731) ; 174.472,47.541 174.472,45.001 v1(174.472,43.731) ; 174.472,52.663 174.472,55.203 174.472,57.743 174.472,60.283 174.472,62.823 174.472,65.363 v1(174.472,66.633) ; 174.472,70.443 174.472,67.903 v1(174.472,66.633) ; 174.472,75.565 174.472,78.105 174.472,80.645 174.472,83.185 174.472,85.725 174.472,88.265 v1(174.472,89.535) ; 174.472,93.345 174.472,90.805 v1(174.472,89.535) ; 182.879,8.764 182.879,11.304 182.879,22.734 ; 182.879,31.666 182.879,34.206 182.879,45.636 ; 182.879,54.568 182.879,57.108 182.879,68.538 ; 182.879,77.47 182.879,80.01 182.879,91.44 ; 186.985,8.764 186.985,22.734 ; 186.985,31.666 186.985,45.636 ; 186.985,54.568 186.985,68.538 ; 186.985,77.47 186.985,91.44 ; 187.112,12.574 v1(188.763,12.574) 189.754,12.574 ; 187.112,20.829 v1(189.754,20.829) ; 187.112,35.476 v1(188.763,35.476) 189.754,35.476 ; 187.112,43.731 v1(189.754,43.731) ; 187.112,58.378 v1(188.763,58.378) 189.754,58.378 ; 187.112,66.633 v1(189.754,66.633) ; 187.112,81.28 v1(188.763,81.28) 189.754,81.28 ; 187.112,89.535 v1(189.754,89.535) ; 189.754,6.859 189.754,9.399 189.754,11.939 189.754,14.479 189.754,17.019 189.754,19.559 v1(189.754,20.829) ; 189.754,24.639 189.754,22.099 v1(189.754,20.829) ; 189.754,29.761 189.754,32.301 189.754,34.841 189.754,37.381 189.754,39.921 189.754,42.461 v1(189.754,43.731) ; 189.754,47.541 189.754,45.001 v1(189.754,43.731) ; 189.754,52.663 189.754,55.203 189.754,57.743 189.754,60.283 189.754,62.823 189.754,65.363 v1(189.754,66.633) ; 189.754,70.443 189.754,67.903 v1(189.754,66.633) ; 189.754,75.565 189.754,78.105 189.754,80.645 189.754,83.185 189.754,85.725 189.754,88.265 v1(189.754,89.535) ; 189.754,93.345 189.754,90.805 v1(189.754,89.535) ; 198.161,8.764 198.161,11.304 198.161,22.734 ; 198.161,31.666 198.161,34.206 198.161,45.636 ; 198.161,54.568 198.161,57.108 198.161,68.538 ; 198.161,77.47 198.161,80.01 198.161,91.44 ; 202.267,8.764 202.267,22.734 ; 202.267,31.666 202.267,45.636 ; 202.267,54.568 202.267,68.538 ; 202.267,77.47 202.267,91.44 ; 202.394,12.574 v1(204.045,12.574) 205.036,12.574 ; 202.394,20.829 v1(205.036,20.829) ; 202.394,35.476 v1(204.045,35.476) 205.036,35.476 ; 202.394,43.731 v1(205.036,43.731) ; 202.394,58.378 v1(204.045,58.378) 205.036,58.378 ; 202.394,66.633 v1(205.036,66.633) ; 202.394,81.28 v1(204.045,81.28) 205.036,81.28 ; 202.394,89.535 v1(205.036,89.535) ; 205.036,6.859 205.036,9.399 205.036,11.939 205.036,14.479 205.036,17.019 205.036,19.559 v1(205.036,20.829) ; 205.036,24.639 205.036,22.099 v1(205.036,20.829) ; 205.036,29.761 205.036,32.301 205.036,34.841 205.036,37.381 205.036,39.921 205.036,42.461 v1(205.036,43.731) ; 205.036,47.541 205.036,45.001 v1(205.036,43.731) ; 205.036,52.663 205.036,55.203 205.036,57.743 205.036,60.283 205.036,62.823 205.036,65.363 v1(205.036,66.633) ; 205.036,70.443 205.036,67.903 v1(205.036,66.633) ; 205.036,75.565 205.036,78.105 205.036,80.645 205.036,83.185 205.036,85.725 205.036,88.265 v1(205.036,89.535) ; 205.036,93.345 205.036,90.805 v1(205.036,89.535) ; 213.443,8.764 213.443,11.304 213.443,22.734 ; 213.443,31.666 213.443,34.206 213.443,45.636 ; 213.443,54.568 213.443,57.108 213.443,68.538 ; 213.443,77.47 213.443,80.01 213.443,91.44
